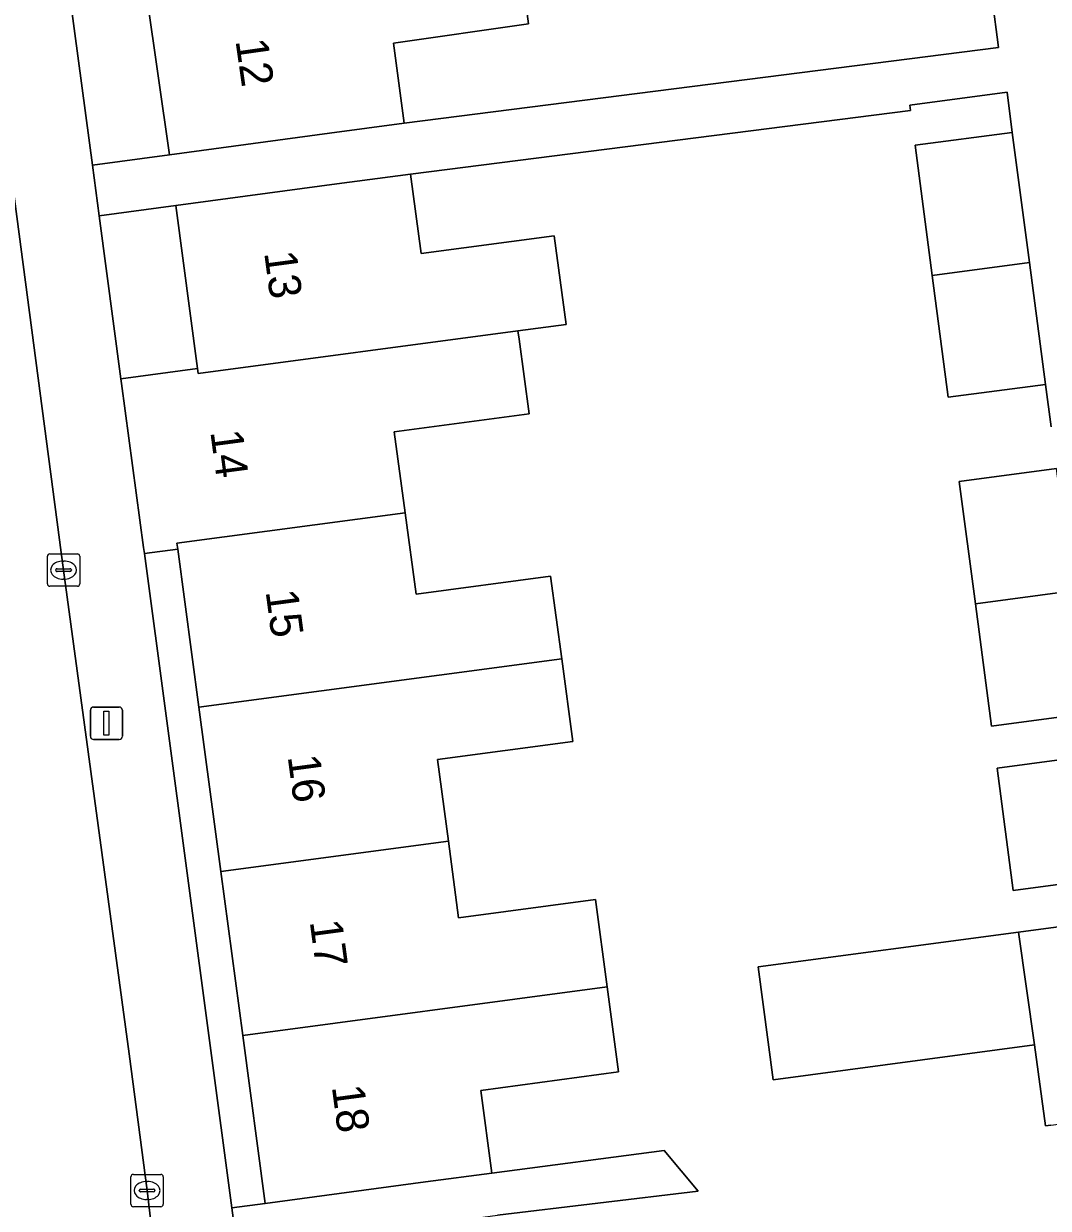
# Model space of a CAD drawing. Extents: x 163147 to 163550, y 380933 to 381639.
# Drawn here: x 163431.58 to 163463.29, y 381183.65 to 381220.32 of the extents above; entities that cross this region are included whole.
import ezdxf

# ---------------------------------------------------------------- set-up
doc = ezdxf.new("R2010")
doc.units = 0
for name, color, linetype in [('IMGEO_Erf', 7, 'Continuous'), ('IMGEO_Kolk', 7, 'Continuous'), ('IMGEO_Lichtmast', 7, 'Continuous'), ('IMGEO_Pand', 7, 'Continuous'), ('IMGEO_Pand_nummerreeks', 7, 'Continuous'), ('IMGEO_Rijbaan_lokaal_open', 7, 'Continuous'), ('IMGEO_Voetpad_open', 7, 'Continuous')]:
    doc.layers.add(name, color=color, linetype=linetype)

msp = doc.modelspace()

# ---------------------------------------------------------------- linework, layer by layer
at = {"layer": 'IMGEO_Erf'}
for points in [[(163446.874, 381222.815), (163447.21, 381220.316), (163443.033, 381219.718), (163443.357, 381217.244), (163461.751, 381219.589), (163461.71, 381219.908), (163461.597, 381220.769)], [(163463.379, 381207.842), (163463.206, 381209.156), (163460.197, 381208.756), (163459.702, 381212.525), (163459.171, 381216.559), (163462.18, 381216.954), (163462.016, 381218.197), (163459.007, 381217.802), (163459.029, 381217.638), (163443.56, 381215.666), (163443.889, 381213.204), (163448.002, 381213.754), (163448.368, 381211.014), (163446.882, 381210.816), (163446.917, 381210.557), (163447.226, 381208.248), (163443.054, 381207.69), (163443.39, 381205.18), (163443.726, 381202.664), (163447.893, 381203.221), (163448.236, 381200.658), (163448.577, 381198.105), (163444.39, 381197.545), (163444.727, 381195.019), (163445.045, 381192.641), (163449.279, 381193.207), (163449.641, 381190.505), (163449.993, 381187.872), (163445.731, 381187.302), (163446.073, 381184.742), (163451.409, 381185.441), (163452.457, 381184.186), (163446.248, 381183.436)], [(163464.546, 381198.975), (163461.537, 381198.574), (163461.039, 381202.365), (163460.54, 381206.155), (163463.548, 381206.555)], [(163465.215, 381193.888), (163462.207, 381193.487), (163461.707, 381197.281), (163464.716, 381197.682)], [(163463.374, 381186.229), (163463.212, 381186.208), (163462.863, 381188.709), (163454.777, 381187.628), (163454.31, 381191.124), (163462.376, 381192.202), (163465.384, 381192.603)]]:
    msp.add_lwpolyline(points, dxfattribs=at)
for points in [[(163435.398, 381221.16), (163433.055, 381220.865), (163433.713, 381215.942), (163436.097, 381216.261)], [(163436.288, 381214.693), (163433.922, 381214.377), (163434.596, 381209.333), (163436.962, 381209.649)], [(163437.685, 381194.081), (163437.006, 381199.161), (163436.351, 381204.059), (163435.32, 381203.921), (163438.023, 381183.666), (163439.059, 381183.804), (163438.364, 381189.002)]]:
    msp.add_lwpolyline(points, close=True, dxfattribs=at)
at = {"layer": 'IMGEO_Kolk'}
for p, q in [((163432.393, 381203.908), (163433.245, 381203.908)), ((163432.318, 381202.982), (163432.318, 381203.834)), ((163432.806, 381203.688), (163432.831, 381203.688)), ((163433.319, 381203.834), (163433.319, 381202.982)), ((163432.577, 381203.402), (163432.577, 381203.414)), ((163433.015, 381203.365), (163432.617, 381203.365)), ((163432.62, 381203.451), (163433.018, 381203.451)), ((163433.061, 381203.414), (163433.061, 381203.402)), ((163433.245, 381202.908), (163432.393, 381202.908)), ((163432.829, 381203.128), (163432.804, 381203.128)), ((163434.903, 381183.776), (163434.903, 381184.628)), ((163434.978, 381184.702), (163435.83, 381184.702)), ((163435.391, 381184.482), (163435.416, 381184.482)), ((163435.904, 381184.628), (163435.904, 381183.776)), ((163435.162, 381184.196), (163435.162, 381184.208)), ((163435.6, 381184.159), (163435.202, 381184.159)), ((163435.205, 381184.245), (163435.603, 381184.245)), ((163435.646, 381184.208), (163435.646, 381184.196)), ((163435.83, 381183.702), (163434.978, 381183.702)), ((163435.414, 381183.922), (163435.389, 381183.922))]:
    msp.add_line(p, q, dxfattribs=at)
for points in [[(163432.393, 381203.908), (163433.245, 381203.908)], [(163432.318, 381202.982), (163432.318, 381203.834)], [(163433.319, 381203.834), (163433.319, 381202.982)], [(163433.245, 381202.908), (163432.393, 381202.908)], [(163434.903, 381183.776), (163434.903, 381184.628)], [(163434.978, 381184.702), (163435.83, 381184.702)], [(163435.904, 381184.628), (163435.904, 381183.776)], [(163435.83, 381183.702), (163434.978, 381183.702)]]:
    msp.add_lwpolyline(points, dxfattribs=at)
for centre, radius, start, end in [((163432.395, 381203.832), 0.0765, 91.552, 178.448), ((163432.395, 381203.832), 0.0765, 91.552, 178.448), ((163433.243, 381203.832), 0.0765, 1.552, 88.448), ((163433.243, 381203.832), 0.0765, 1.552, 88.448), ((163432.617, 381203.411), 0.0403, 85.8775, 175.7526), ((163432.614, 381203.401), 0.0366, 178.938, 274.7102), ((163433.018, 381203.408), 0.043, 264.8664, 352.4533), ((163433.022, 381203.413), 0.0386, 1.7309, 96.639), ((163432.395, 381202.984), 0.0765, 181.552, 268.448), ((163432.395, 381202.984), 0.0765, 181.552, 268.448), ((163433.243, 381202.984), 0.0765, 271.552, 358.448), ((163433.243, 381202.984), 0.0765, 271.552, 358.448), ((163434.98, 381184.626), 0.0765, 91.552, 178.448), ((163434.98, 381184.626), 0.0765, 91.552, 178.448), ((163435.828, 381184.626), 0.0765, 1.552, 88.448), ((163435.828, 381184.626), 0.0765, 1.552, 88.448), ((163435.202, 381184.205), 0.0403, 85.8775, 175.7526), ((163435.199, 381184.195), 0.0366, 178.938, 274.7102), ((163435.603, 381184.202), 0.043, 264.8664, 352.4533), ((163435.607, 381184.207), 0.0386, 1.7309, 96.639), ((163434.98, 381183.778), 0.0765, 181.552, 268.448), ((163434.98, 381183.778), 0.0765, 181.552, 268.448), ((163435.828, 381183.778), 0.0765, 271.552, 358.448), ((163435.828, 381183.778), 0.0765, 271.552, 358.448)]:
    msp.add_arc(centre, radius, start, end, dxfattribs=at)
for centre, major_axis, ratio, start_param, end_param in [((163432.805, 381203.408), (-0.387, 0.002), 0.722429, 4.712389, 7.853982), ((163432.83, 381203.408), (-0.39, 0.002), 0.717154, 1.570796, 4.712389), ((163435.39, 381184.202), (-0.387, 0.002), 0.722429, 4.712389, 7.853982), ((163435.415, 381184.202), (-0.39, 0.002), 0.717154, 1.570796, 4.712389)]:
    msp.add_ellipse(centre, major_axis=major_axis, ratio=ratio, start_param=start_param, end_param=end_param, dxfattribs=at)
at = {"layer": 'IMGEO_Lichtmast'}
for p, q in [((163433.748, 381199.168), (163434.538, 381199.168)), ((163434.538, 381199.168), (163433.748, 381199.168)), ((163433.648, 381198.268), (163433.648, 381199.068)), ((163433.648, 381199.068), (163433.648, 381198.268)), ((163434.638, 381199.068), (163434.638, 381198.268)), ((163434.638, 381198.268), (163434.638, 381199.068)), ((163434.538, 381198.168), (163433.748, 381198.168)), ((163433.748, 381198.168), (163434.538, 381198.168))]:
    msp.add_line(p, q, dxfattribs=at)
msp.add_lwpolyline([(163434.068, 381199.043), (163434.218, 381199.043), (163434.218, 381198.293), (163434.068, 381198.293), (163434.068, 381199.043)], dxfattribs=at)
for centre, start, end in [((163433.748, 381199.068), 90, 180), ((163433.748, 381199.068), 90, 180), ((163434.538, 381199.068), 0, 90), ((163434.538, 381199.068), 360, 90), ((163433.748, 381198.268), 180, 270), ((163433.748, 381198.268), 180, 270), ((163434.538, 381198.268), 270, 0), ((163434.538, 381198.268), 270, 0)]:
    msp.add_arc(centre, 0.1, start, end, dxfattribs=at)
at = {"layer": 'IMGEO_Pand'}
for points in [[(163443.033, 381219.718), (163447.21, 381220.316), (163446.874, 381222.815), (163445.477, 381222.629), (163435.38, 381221.288), (163435.398, 381221.16), (163436.097, 381216.261), (163441.052, 381216.932), (163443.357, 381217.244)], [(163462.18, 381216.954), (163459.171, 381216.559), (163459.702, 381212.525), (163462.71, 381212.926)], [(163448.002, 381213.754), (163443.889, 381213.204), (163443.56, 381215.666), (163441.278, 381215.361), (163436.288, 381214.693), (163436.962, 381209.649), (163436.982, 381209.496), (163446.882, 381210.816), (163448.368, 381211.014)], [(163462.71, 381212.926), (163459.702, 381212.525), (163460.197, 381208.756), (163463.206, 381209.156)], [(163447.226, 381208.248), (163446.917, 381210.557), (163446.882, 381210.816), (163436.982, 381209.496), (163436.962, 381209.649), (163434.596, 381209.333), (163434.616, 381209.181), (163435.296, 381204.102), (163435.32, 381203.921), (163436.351, 381204.059), (163436.327, 381204.239), (163443.39, 381205.18), (163443.054, 381207.69)], [(163463.548, 381206.555), (163460.54, 381206.155), (163461.039, 381202.365), (163464.047, 381202.766)], [(163443.39, 381205.18), (163436.327, 381204.239), (163436.351, 381204.059), (163437.006, 381199.161), (163448.236, 381200.658), (163447.893, 381203.221), (163443.726, 381202.664)], [(163464.047, 381202.766), (163461.039, 381202.365), (163461.537, 381198.574), (163464.546, 381198.975)], [(163448.236, 381200.658), (163437.006, 381199.161), (163437.685, 381194.081), (163444.727, 381195.019), (163444.39, 381197.545), (163448.577, 381198.105)], [(163464.716, 381197.682), (163461.707, 381197.281), (163462.207, 381193.487), (163465.215, 381193.888)], [(163438.364, 381189.002), (163449.641, 381190.505), (163449.279, 381193.207), (163445.045, 381192.641), (163444.727, 381195.019), (163437.685, 381194.081)], [(163465.384, 381192.603), (163462.376, 381192.202), (163462.863, 381188.709), (163463.212, 381186.208), (163463.374, 381186.229), (163463.614, 381186.261), (163466.221, 381186.604)], [(163462.376, 381192.202), (163454.31, 381191.124), (163454.777, 381187.628), (163462.863, 381188.709)], [(163438.364, 381189.002), (163439.059, 381183.804), (163444.015, 381184.467), (163446.073, 381184.742), (163445.731, 381187.302), (163449.993, 381187.872), (163449.641, 381190.505)]]:
    msp.add_lwpolyline(points, close=True, dxfattribs=at)
at = {"layer": 'IMGEO_Rijbaan_lokaal_open'}
msp.add_lwpolyline([(163435.88, 381180.272), (163435.633, 381182.277), (163435.404, 381184.201), (163434.853, 381188.435), (163432.818, 381203.407), (163430.773, 381218.81), (163425.989, 381218.194), (163426.029, 381217.897), (163430.333, 381185.704), (163430.851, 381181.833)], dxfattribs=at)
at = {"layer": 'IMGEO_Voetpad_open'}
for points in [[(163419.541, 381301.698), (163419.608, 381301.196), (163421.129, 381289.848), (163421.495, 381287.123), (163426.471, 381250), (163430.261, 381222.635), (163430.41, 381221.543), (163430.773, 381218.81), (163432.818, 381203.407), (163434.853, 381188.435), (163435.404, 381184.201), (163435.633, 381182.277), (163435.88, 381180.272), (163436.282, 381176.303), (163436.423, 381174.825), (163436.736, 381171.03), (163436.749, 381170.87), (163436.756, 381170.797), (163436.763, 381170.724), (163437.048, 381167.531), (163437.11, 381166.833)], [(163438.198, 381182.356), (163438.023, 381183.666), (163435.32, 381203.921), (163435.296, 381204.102), (163434.616, 381209.181), (163434.596, 381209.333), (163433.922, 381214.377), (163433.713, 381215.942), (163433.055, 381220.865), (163433.039, 381220.977), (163432.314, 381226.058), (163432.283, 381226.275), (163429.579, 381246.702), (163429.432, 381247.82), (163429.143, 381250), (163426.754, 381268.057), (163426.086, 381273.18), (163426.051, 381273.449), (163425.393, 381278.278), (163425.235, 381279.434), (163424.816, 381282.506), (163423.226, 381294.162)], [(163461.597, 381220.769), (163461.71, 381219.908), (163461.751, 381219.589), (163443.357, 381217.244), (163441.052, 381216.932), (163436.097, 381216.261), (163433.713, 381215.942), (163433.922, 381214.377), (163436.288, 381214.693), (163441.278, 381215.361), (163443.56, 381215.666), (163459.029, 381217.638), (163459.007, 381217.802), (163462.016, 381218.197), (163462.18, 381216.954), (163462.71, 381212.926), (163463.206, 381209.156), (163463.379, 381207.842)]]:
    msp.add_lwpolyline(points, dxfattribs=at)
msp.add_lwpolyline([(163451.409, 381185.441), (163446.073, 381184.742), (163444.015, 381184.467), (163439.059, 381183.804), (163438.023, 381183.666), (163438.198, 381182.356), (163439.219, 381182.492), (163444.133, 381183.152), (163446.248, 381183.436), (163452.457, 381184.186)], close=True, dxfattribs=at)

# ---------------------------------------------------------------- texts
at = {"layer": 'IMGEO_Pand_nummerreeks'}
for s, rotation, p in [('12', 278.1186, (163438.137, 381219.797)), ('13', 277.6087, (163439.025, 381213.233)), ('14', 277.6201, (163437.358, 381207.691)), ('15', 277.6144, (163439.069, 381202.747)), ('16', 277.615, (163439.752, 381197.638)), ('17', 277.615, (163440.435, 381192.53)), ('18', 277.615, (163441.118, 381187.418))]:
    msp.add_text(s, height=1, rotation=rotation, dxfattribs=at).set_placement(p)

doc.saveas('drawing.dxf')
